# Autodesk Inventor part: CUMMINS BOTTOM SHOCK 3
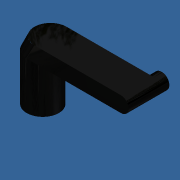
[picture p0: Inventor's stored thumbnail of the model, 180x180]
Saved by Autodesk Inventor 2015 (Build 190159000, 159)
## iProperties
Created: 2014-10
Part Number: CUMMINS BOTTOM SHOCK 3
Material: Generic
Document SubType Name: Modeling
Designer: caovt
Density: 1 g/cm^3
Appearance: Default
Author: caovt
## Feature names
1. Extrusion1
2. Extrusion2
3. Sweep1
4. Extrusion10
5. Extrusion11
## Parameters: d0 = 4.572 mm, d1 = 27.94 mm, d2 = 20.35054 mm, d3 = 25.65051 mm, d4 = 9.525 mm, d5 = 0, d6 = 9.525 mm, d7 = 13.97 mm, d8 = 0, d9 = 0, d10 = 0, d35 = 2.54 mm, d36 = 0, d37 = 2.54 mm, d38 = 0
